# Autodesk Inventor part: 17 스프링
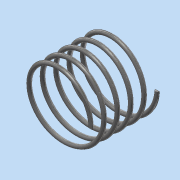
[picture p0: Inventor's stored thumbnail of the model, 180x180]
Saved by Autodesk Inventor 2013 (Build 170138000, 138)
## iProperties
Created: 2016-06
Part Number: 17 스프링
Material: 강철, 탄소
Document SubType Name: Modeling
Designer: Administrator
Density: 7.87 g/cm^3
Mass: 1.62957 g
Surface Area: 8.35994 cm^2
Volume: 0.207061 cm^3
Author: Administrator
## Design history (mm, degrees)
sketch "스케치1"
  geometry: L1 (0, 0)-(8.5, 0); L2 (8.5, 0)-(8.5, 16.67); L3 (8.5, 16.67)-(0, 16.67); L4 (0, 16.67)-(0, 0); C1 r 0.5 at (8.5, 0)
  constraints: 8 end point, 2 parallel, 1 centre point, 1 coincident, 1 horizontal, 1 perpendicular
  dimensions: "d0" = 16.66987 distance of L3.end L1.start (derived); "d1" = 1 diameter of C1; "d2" = 17 diameter of L2 L4
feature "코일1" sketch "스케치1" pitch "d3" = 10; turns "d5" = 5; dims "d4" = 16.66987 (= d0), "d6" = 0, angle "d7" = 90 deg, angle "d8" = 90 deg, "d9" = 0, "d10" = 0
sketch "스케치2"
  geometry: L1 (0, 15)-(16.67, 15); L2 (16.67, 15)-(16.67, -15); L3 (16.67, -15)-(0, -15); L4 (0, -15)-(0, 15); 4 further points
  constraints: 8 end point, 2 coincident, 2 midpoint, 2 parallel, 1 horizontal, 1 perpendicular
  dimensions: "d11" = 30 distance of L1.end L2.end
extrude "돌출1" sketch "스케치2" stored distance "d13" = 50; taper "d14" = 0 deg
node "솔리드1"
